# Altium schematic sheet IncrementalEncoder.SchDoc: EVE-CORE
size A4; Organization: Ingenia Motion Control; Address1: Carrer Avila, 124, 2B; Address2: 08018 Barcelona Spain; Address3: www.ingeniamc.com; Address4: www.ingeniamc.com; Documentation: https://doc.ingeniamc.com/x/coAZBg
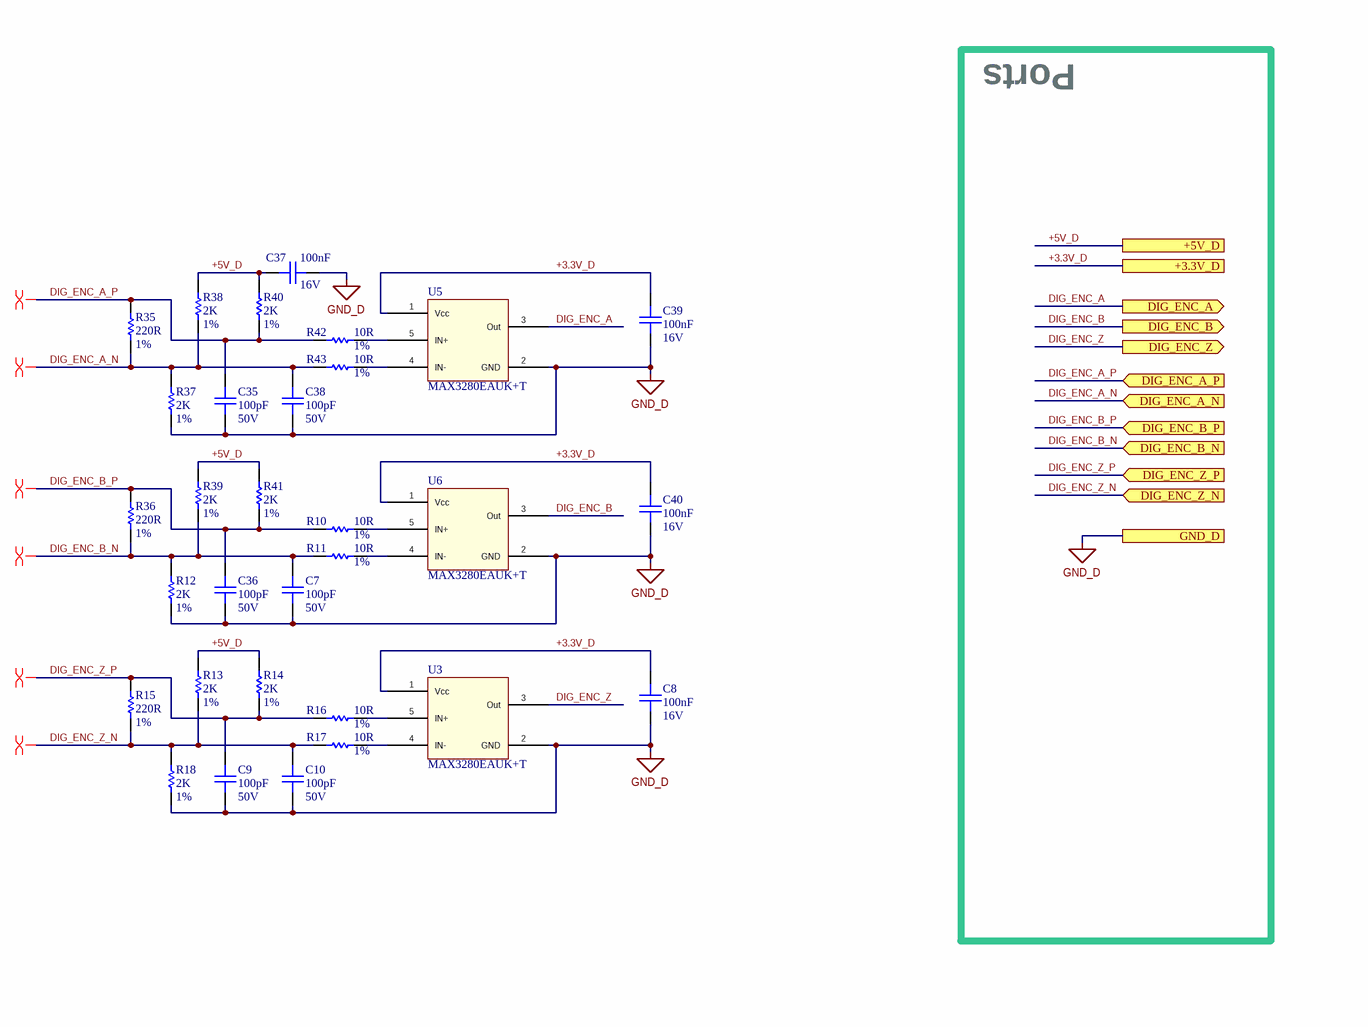
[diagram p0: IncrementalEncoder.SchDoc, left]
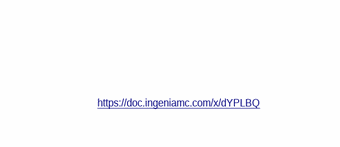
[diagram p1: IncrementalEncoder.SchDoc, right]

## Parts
C7  value 100pF  Voltage: 50V  [C_0402]  (hidden comment: C_0402--100pF--50V)
C8  value 100nF  Voltage: 16V  [C_0402]  (hidden comment: C_0402--100nF--16V)
C9  value 100pF  Voltage: 50V  [C_0402]  (hidden comment: C_0402--100pF--50V)
C10  value 100pF  Voltage: 50V  [C_0402]  (hidden comment: C_0402--100pF--50V)
C35  value 100pF  Voltage: 50V  [C_0402]  (hidden comment: C_0402--100pF--50V)
C36  value 100pF  Voltage: 50V  [C_0402]  (hidden comment: C_0402--100pF--50V)
C37  value 100nF  Voltage: 16V  [C_0402]  (hidden comment: C_0402--100nF--16V)
C38  value 100pF  Voltage: 50V  [C_0402]  (hidden comment: C_0402--100pF--50V)
C39  value 100nF  Voltage: 16V  [C_0402]  (hidden comment: C_0402--100nF--16V)
C40  value 100nF  Voltage: 16V  [C_0402]  (hidden comment: C_0402--100nF--16V)
R10  value 10R  Tolerance: 1%  [R_0603]  (hidden comment: R_0603--10R--1%)
R11  value 10R  Tolerance: 1%  [R_0603]  (hidden comment: R_0603--10R--1%)
R12  value 2K  Tolerance: 1%  [R_0402]  (hidden comment: R_0402--2K--1%)
R13  value 2K  Tolerance: 1%  [R_0402]  (hidden comment: R_0402--2K--1%)
R14  value 2K  Tolerance: 1%  [R_0402]  (hidden comment: R_0402--2K--1%)
R15  value 220R  Tolerance: 1%  [R_0603]  (hidden comment: R_0603--220R--1%)
R16  value 10R  Tolerance: 1%  [R_0603]  (hidden comment: R_0603--10R--1%)
R17  value 10R  Tolerance: 1%  [R_0603]  (hidden comment: R_0603--10R--1%)
R18  value 2K  Tolerance: 1%  [R_0402]  (hidden comment: R_0402--2K--1%)
R35  value 220R  Tolerance: 1%  [R_0603]  (hidden comment: R_0603--220R--1%)
R36  value 220R  Tolerance: 1%  [R_0603]  (hidden comment: R_0603--220R--1%)
R37  value 2K  Tolerance: 1%  [R_0402]  (hidden comment: R_0402--2K--1%)
R38  value 2K  Tolerance: 1%  [R_0402]  (hidden comment: R_0402--2K--1%)
R39  value 2K  Tolerance: 1%  [R_0402]  (hidden comment: R_0402--2K--1%)
R40  value 2K  Tolerance: 1%  [R_0402]  (hidden comment: R_0402--2K--1%)
R41  value 2K  Tolerance: 1%  [R_0402]  (hidden comment: R_0402--2K--1%)
R42  value 10R  Tolerance: 1%  [R_0603]  (hidden comment: R_0603--10R--1%)
R43  value 10R  Tolerance: 1%  [R_0603]  (hidden comment: R_0603--10R--1%)
U3  MAX3280EAUK+T  [SOT23-5N]
U5  MAX3280EAUK+T  [SOT23-5N]
U6  MAX3280EAUK+T  [SOT23-5N]

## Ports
+3.3V_D, +5V_D, DIG_ENC_A (out), DIG_ENC_A_N (in), DIG_ENC_A_P (in), DIG_ENC_B (out), DIG_ENC_B_N (in), DIG_ENC_B_P (in), DIG_ENC_Z (out), DIG_ENC_Z_N (in), DIG_ENC_Z_P (in), GND_D

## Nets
GND_D: C7.2 C8.2 C9.2 C10.2 C35.2 C36.2 C37.2 C38.2 C39.2 C40.2 R12.2 R18.2 R37.2 U3.2(GND) U5.2(GND) U6.2(GND) ; port GND_D
+3.3V_D: C8.1 C39.1 C40.1 U3.1(Vcc) U5.1(Vcc) U6.1(Vcc) ; port +3.3V_D
+5V_D: C37.1 R13.2 R14.2 R38.2 R39.2 R40.2 R41.2 ; port +5V_D
DIG_ENC_A: U5.3(Out) ; port DIG_ENC_A
DIG_ENC_A_N: C38.1 R35.2 R37.1 R38.1 R43.1 ; port DIG_ENC_A_N
DIG_ENC_A_P: C35.1 R35.1 R40.1 R42.1 ; port DIG_ENC_A_P
DIG_ENC_B: U6.3(Out) ; port DIG_ENC_B
DIG_ENC_B_N: C7.1 R11.1 R12.1 R36.2 R39.1 ; port DIG_ENC_B_N
DIG_ENC_B_P: C36.1 R10.1 R36.1 R41.1 ; port DIG_ENC_B_P
DIG_ENC_Z: U3.3(Out) ; port DIG_ENC_Z
DIG_ENC_Z_N: C10.1 R13.1 R15.2 R17.1 R18.1 ; port DIG_ENC_Z_N
DIG_ENC_Z_P: C9.1 R14.1 R15.1 R16.1 ; port DIG_ENC_Z_P
NetR10_2: R10.2 U6.5(IN+)
NetR11_2: R11.2 U6.4(IN-)
NetR16_2: R16.2 U3.5(IN+)
NetR17_2: R17.2 U3.4(IN-)
NetR42_2: R42.2 U5.5(IN+)
NetR43_2: R43.2 U5.4(IN-)

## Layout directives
differential pair: DIG_ENC_A_N, DIG_ENC_A_P, DIG_ENC_B_N, DIG_ENC_B_P, DIG_ENC_Z_N, DIG_ENC_Z_P

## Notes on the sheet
- Ports
- https://doc.ingeniamc.com/x/dYPLBQ

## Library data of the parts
C7 C9 C10 C35 C36 C38 = C_0402[[/\]]100pF[[/\]]50V: CAP CER 100pF 50V NP0/C0G 0402; ManufacturerName: Yageo; ManufacturerPN: CC0402JRNPO9BN101; AlternativeManufacturer: Kemet; IsPreferred: 0; IngeniaID: 1451; AdditionalInformation: NP0; AlternativePN: C0402H101J5GAFT1K0; MTBF55h: 77243743; TemperatureMaxC: 125; TemperatureMinC: -55
C8 C37 C39 C40 = C_0402[[/\]]100nF[[/\]]16V: CAP CER 100nF 16V X7R 0402; ManufacturerName: Murata; ManufacturerPN: GRM155R71C104KA88D; AlternativeManufacturer: Wurth; IsPreferred: 1; IngeniaID: 672; InternalStock: 0; TemperatureMaxC: 125; TemperatureMinC: -55; MTBF55h: 36129613; AlternativePN: 885012205037
R10 R11 R16 R17 R42 R43 = R_0603[[/\]]10R[[/\]]1%: Resistor, 0603, 10ohm, 1%; ManufacturerName: Multicomp; ManufacturerPN: MC 0.063W 0603 1% 10R; AlternativeManufacturer: Yageo; IsPreferred: 0; IsGeneric: 1; IngeniaID: 781; AlternativePN: RC0603FR-0710RL; TemperatureMaxC: 155; TemperatureMinC: -55
R12-R14 R18 R37-R41 = R_0402[[/\]]2K[[/\]]1%: RES 2K OHM 1/16W 1% 0402 SMD; ManufacturerName: Stackpole Electronics; ManufacturerPN: RMCF0402FT2K00; AlternativeManufacturer: Panasonic Electronic Components; IsPreferred: 0; IsGeneric: 1; IngeniaID: 689; AlternativePN: ERJ-2RKF2001X; MTBF55h: 91649788; TemperatureMaxC: 155; TemperatureMinC: -55
R15 R35 R36 = R_0603[[/\]]220R[[/\]]1%: Resistor 1%; ManufacturerName: Panasonic; ManufacturerPN: ERJ3EKF2200V; AlternativeManufacturer: Yageo; IsPreferred: 0; IsGeneric: 1; IngeniaID: 822; TemperatureMaxC: 155; TemperatureMinC: -55; AlternativePN: RC0603FR-07220RL
U3 U5 U6 = MAX3280EAUK+T: Single differential line receiver RS422 RS485 52 MBps 125ºC; ManufacturerName: Maxim Integrated; IsPreferred: 1; IsGeneric: 0; IngeniaID: 2197; TemperatureMaxC: 125; TemperatureMinC: -40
